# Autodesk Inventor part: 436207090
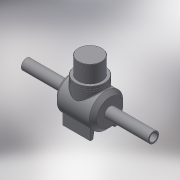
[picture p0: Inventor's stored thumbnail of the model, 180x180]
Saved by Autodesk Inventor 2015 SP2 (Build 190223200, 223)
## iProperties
Created: 2017-08
Part Number: 436207090
Material: Generic
Description: PLASSON PE BALL VALVE 90
Document SubType Name: Modeling
Designer: Кирилл
Density: 1 g/cm^3
Appearance: Default
Author: Кирилл
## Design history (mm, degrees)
derived "436207.ipt"
feature "Solid1::436207.ipt"
feature "Solid2::436207.ipt"
tag "TaggingFeature1"
body "Solid1"
other parameters: "d3" = 176, "d5" = 67.5, "d6" = 16.5, "d10" = 85, "d11" = 68, "d12" = 0.85, "d13" = 4, "d14" = 4, "d16" = 100 deg, "d18" = 16, "d20" = 93, "d21" = 0, "d22" = 0.85, "d26" = 8, "d28" = 0, "d29" = 1.7, "s_" = 8, "L_1" = 176, "B_" = 93, "E_1" = 85
